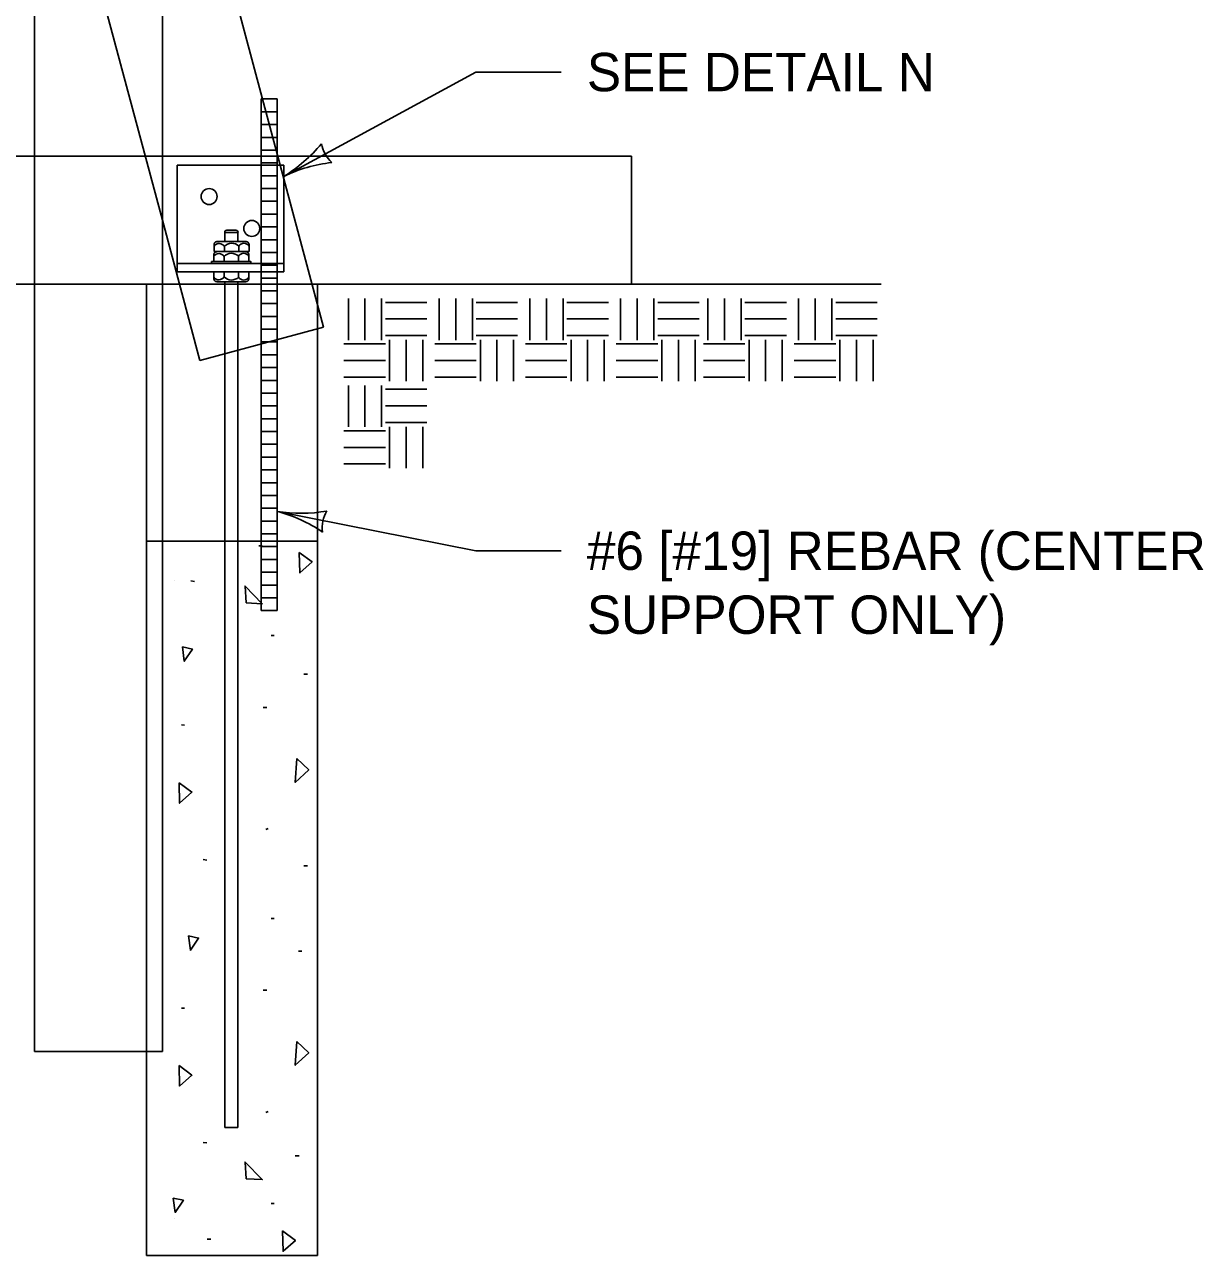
# Model space of a CAD drawing. Extents: x 49991.4 to 50021, y 49987.6 to 50011.4.
# Drawn here: x 50004.937 to 50006.78, y 49995.265 to 49997.19 of the extents above; entities that cross this region are included whole.
import ezdxf

# ---------------------------------------------------------------- set-up
doc = ezdxf.new("R2010")
doc.units = 0
for name, color, linetype in [('Level 1', 7, 'Continuous'), ('Level 2', 7, 'Continuous'), ('Level 3', 7, 'Continuous'), ('Level 4', 7, 'Continuous')]:
    doc.layers.add(name, color=color, linetype=linetype)

msp = doc.modelspace()

# ---------------------------------------------------------------- linework, layer by layer
at = {"layer": 'Level 1'}
for p, q in [((50004.9525, 49995.5838), (50004.9525, 49998.3434)), ((50005.1525, 49998.3434), (50005.1525, 49995.5838)), ((50005.3364, 49996.97), (50005.1525, 49997.6571)), ((50005.3087, 49997.0734), (50005.3316, 49997.0734)), ((50005.3316, 49996.988), (50005.3316, 49997.0734)), ((50005.3141, 49997.0534), (50005.3316, 49997.0534)), ((50005.3194, 49997.0334), (50005.3316, 49997.0334)), ((50005.3248, 49997.0134), (50005.3316, 49997.0134)), ((50005.3302, 49996.9934), (50005.3316, 49996.9934)), ((50001.0856, 49996.9838), (50004.9525, 49996.9838)), ((50005.3327, 49996.9838), (50005.8856, 49996.9838)), ((50005.8856, 49996.9838), (50005.8856, 49996.7838)), ((50005.1754, 49996.8033), (50005.1754, 49996.97)), ((50005.1754, 49996.97), (50005.3421, 49996.97)), ((50005.3421, 49996.8033), (50005.3421, 49996.97)), ((50005.4043, 49996.7164), (50005.3421, 49996.9488)), ((50005.2111, 49996.6647), (50005.1525, 49996.8838)), ((50005.2497, 49996.8648), (50005.2705, 49996.8648)), ((50005.2497, 49996.8648), (50005.2497, 49996.8506)), ((50005.253, 49996.8681), (50005.2672, 49996.8681)), ((50005.2705, 49996.8648), (50005.2705, 49996.8506)), ((50005.233, 49996.8444), (50005.233, 49996.8348)), ((50005.2818, 49996.8506), (50005.2391, 49996.8506)), ((50005.2492, 49996.8428), (50005.2492, 49996.8348)), ((50005.2717, 49996.8348), (50005.2717, 49996.8433)), ((50005.288, 49996.8348), (50005.288, 49996.8444)), ((50005.2325, 49996.8286), (50005.2325, 49996.8192)), ((50005.233, 49996.8348), (50005.288, 49996.8348)), ((50005.2488, 49996.827), (50005.2488, 49996.8192)), ((50005.2713, 49996.8192), (50005.2713, 49996.8275)), ((50005.2875, 49996.8192), (50005.2875, 49996.8286)), ((50005.1754, 49996.816), (50005.3421, 49996.816)), ((50005.1754, 49996.8033), (50005.3421, 49996.8033)), ((50005.2326, 49996.7938), (50005.2326, 49996.8033)), ((50005.2489, 49996.7954), (50005.2489, 49996.8033)), ((50005.2714, 49996.8033), (50005.2714, 49996.7949)), ((50005.2876, 49996.8033), (50005.2876, 49996.7938)), ((50004.9525, 49996.7838), (50000.2807, 49996.7838)), ((50005.1792, 49996.7838), (50005.1525, 49996.7838)), ((50005.2815, 49996.7876), (50005.2388, 49996.7876)), ((50005.2497, 49996.7876), (50005.2497, 49995.4651)), ((50005.2705, 49996.7876), (50005.2705, 49995.4651)), ((50006.2762, 49996.7838), (50005.3863, 49996.7838)), ((50005.4431, 49996.7613), (50005.4431, 49996.6965)), ((50005.469, 49996.7613), (50005.469, 49996.6965)), ((50005.495, 49996.7613), (50005.495, 49996.6965)), ((50005.585, 49996.7613), (50005.585, 49996.6965)), ((50005.6109, 49996.7613), (50005.6109, 49996.6965)), ((50005.6369, 49996.7613), (50005.6369, 49996.6965)), ((50005.7269, 49996.7613), (50005.7269, 49996.6965)), ((50005.7528, 49996.7613), (50005.7528, 49996.6965)), ((50005.7788, 49996.7613), (50005.7788, 49996.6965)), ((50005.8688, 49996.7613), (50005.8688, 49996.6965)), ((50005.8947, 49996.7613), (50005.8947, 49996.6965)), ((50005.9207, 49996.7613), (50005.9207, 49996.6965)), ((50006.0052, 49996.7613), (50006.0052, 49996.6965)), ((50006.0311, 49996.7613), (50006.0311, 49996.6965)), ((50006.0571, 49996.7613), (50006.0571, 49996.6965)), ((50006.1471, 49996.7613), (50006.1471, 49996.6965)), ((50006.173, 49996.7613), (50006.173, 49996.6965)), ((50006.199, 49996.7613), (50006.199, 49996.6965)), ((50005.501, 49996.7553), (50005.5658, 49996.7553)), ((50005.6429, 49996.7553), (50005.7077, 49996.7553)), ((50005.7848, 49996.7553), (50005.8496, 49996.7553)), ((50005.9267, 49996.7553), (50005.9915, 49996.7553)), ((50006.0631, 49996.7553), (50006.1279, 49996.7553)), ((50006.205, 49996.7553), (50006.2698, 49996.7553)), ((50005.501, 49996.7294), (50005.5658, 49996.7294)), ((50005.6429, 49996.7294), (50005.7077, 49996.7294)), ((50005.7848, 49996.7294), (50005.8496, 49996.7294)), ((50005.9267, 49996.7294), (50005.9915, 49996.7294)), ((50006.0631, 49996.7294), (50006.1279, 49996.7294)), ((50006.205, 49996.7294), (50006.2698, 49996.7294)), ((50005.2111, 49996.6647), (50005.4043, 49996.7164)), ((50005.501, 49996.7034), (50005.5658, 49996.7034)), ((50005.6429, 49996.7034), (50005.7077, 49996.7034)), ((50005.7848, 49996.7034), (50005.8496, 49996.7034)), ((50005.9267, 49996.7034), (50005.9915, 49996.7034)), ((50006.0631, 49996.7034), (50006.1279, 49996.7034)), ((50006.205, 49996.7034), (50006.2698, 49996.7034)), ((50005.3066, 49996.6903), (50005.3066, 49996.3821)), ((50005.3184, 49996.6934), (50005.3316, 49996.6934)), ((50005.3316, 49996.3821), (50005.3316, 49996.6969)), ((50005.4361, 49996.6905), (50005.501, 49996.6905)), ((50005.5075, 49996.6969), (50005.5075, 49996.6321)), ((50005.5334, 49996.6969), (50005.5334, 49996.6321)), ((50005.5594, 49996.6969), (50005.5594, 49996.6321)), ((50005.578, 49996.6905), (50005.6429, 49996.6905)), ((50005.6494, 49996.6969), (50005.6494, 49996.6321)), ((50005.6753, 49996.6969), (50005.6753, 49996.6321)), ((50005.7013, 49996.6969), (50005.7013, 49996.6321)), ((50005.7199, 49996.6905), (50005.7848, 49996.6905)), ((50005.7913, 49996.6969), (50005.7913, 49996.6321)), ((50005.8172, 49996.6969), (50005.8172, 49996.6321)), ((50005.8432, 49996.6969), (50005.8432, 49996.6321)), ((50005.8618, 49996.6905), (50005.9267, 49996.6905)), ((50005.9332, 49996.6969), (50005.9332, 49996.6321)), ((50005.9591, 49996.6969), (50005.9591, 49996.6321)), ((50005.9851, 49996.6969), (50005.9851, 49996.6321)), ((50005.9982, 49996.6905), (50006.0631, 49996.6905)), ((50006.0696, 49996.6969), (50006.0696, 49996.6321)), ((50006.0955, 49996.6969), (50006.0955, 49996.6321)), ((50006.1215, 49996.6969), (50006.1215, 49996.6321)), ((50006.1401, 49996.6905), (50006.205, 49996.6905)), ((50006.2115, 49996.6969), (50006.2115, 49996.6321)), ((50006.2374, 49996.6969), (50006.2374, 49996.6321)), ((50006.2634, 49996.6969), (50006.2634, 49996.6321)), ((50005.3066, 49996.6734), (50005.3316, 49996.6734)), ((50005.4361, 49996.6645), (50005.501, 49996.6645)), ((50005.578, 49996.6645), (50005.6429, 49996.6645)), ((50005.7199, 49996.6645), (50005.7848, 49996.6645)), ((50005.8618, 49996.6645), (50005.9267, 49996.6645)), ((50005.9982, 49996.6645), (50006.0631, 49996.6645)), ((50006.1401, 49996.6645), (50006.205, 49996.6645)), ((50005.3066, 49996.6534), (50005.3316, 49996.6534)), ((50005.3066, 49996.6334), (50005.3316, 49996.6334)), ((50005.4361, 49996.6386), (50005.501, 49996.6386)), ((50005.4431, 49996.6254), (50005.4431, 49996.5606)), ((50005.469, 49996.6254), (50005.469, 49996.5606)), ((50005.495, 49996.6254), (50005.495, 49996.5606)), ((50005.578, 49996.6386), (50005.6429, 49996.6386)), ((50005.7199, 49996.6386), (50005.7848, 49996.6386)), ((50005.8618, 49996.6386), (50005.9267, 49996.6386)), ((50005.9982, 49996.6386), (50006.0631, 49996.6386)), ((50006.1401, 49996.6386), (50006.205, 49996.6386)), ((50005.3066, 49996.6134), (50005.3316, 49996.6134)), ((50005.501, 49996.6194), (50005.5658, 49996.6194)), ((50005.3066, 49996.5934), (50005.3316, 49996.5934)), ((50005.501, 49996.5935), (50005.5658, 49996.5935)), ((50005.3066, 49996.5734), (50005.3316, 49996.5734)), ((50005.3066, 49996.5534), (50005.3316, 49996.5534)), ((50005.4361, 49996.5546), (50005.501, 49996.5546)), ((50005.501, 49996.5675), (50005.5658, 49996.5675)), ((50005.5075, 49996.561), (50005.5075, 49996.4962)), ((50005.5334, 49996.561), (50005.5334, 49996.4962)), ((50005.5594, 49996.561), (50005.5594, 49996.4962)), ((50005.3066, 49996.5334), (50005.3316, 49996.5334)), ((50005.3066, 49996.5134), (50005.3316, 49996.5134)), ((50005.4361, 49996.5286), (50005.501, 49996.5286)), ((50005.3066, 49996.4934), (50005.3316, 49996.4934)), ((50005.4361, 49996.5027), (50005.501, 49996.5027)), ((50005.3066, 49996.4734), (50005.3316, 49996.4734)), ((50005.3066, 49996.4534), (50005.3316, 49996.4534)), ((50005.3066, 49996.4334), (50005.3316, 49996.4334)), ((50005.3066, 49996.4134), (50005.3316, 49996.4134)), ((50005.1525, 49996.3821), (50005.3947, 49996.3821)), ((50005.3066, 49996.3934), (50005.3316, 49996.3934)), ((50005.3947, 49995.2651), (50005.3947, 49996.3821)), ((50005.3033, 49996.3744), (50005.3083, 49996.3744)), ((50005.1711, 49996.32), (50005.1711, 49996.32)), ((50005.1967, 49996.32), (50005.2023, 49996.3187)), ((50005.3223, 49996.2346), (50005.3273, 49996.2346)), ((50005.3733, 49996.1739), (50005.379, 49996.1739)), ((50005.3098, 49996.122), (50005.3155, 49996.122)), ((50005.1823, 49996.0946), (50005.1868, 49996.094)), ((50005.3138, 49995.9309), (50005.3178, 49995.9326)), ((50005.2161, 49995.8844), (50005.222, 49995.8832)), ((50005.3733, 49995.874), (50005.379, 49995.874)), ((50005.3223, 49995.7919), (50005.3273, 49995.7919)), ((50005.365, 49995.7409), (50005.3705, 49995.7409)), ((50005.1525, 49995.6785), (50005.1525, 49995.6785)), ((50005.3098, 49995.6796), (50005.3155, 49995.6796)), ((50005.1823, 49995.6517), (50005.1868, 49995.6517)), ((50005.1525, 49995.5838), (50004.9525, 49995.5838)), ((50005.1274, 49995.5838), (50005.1274, 49995.2651)), ((50005.3138, 49995.4884), (50005.3178, 49995.4902)), ((50005.2497, 49995.4651), (50005.2705, 49995.4651)), ((50005.2161, 49995.4416), (50005.222, 49995.4409)), ((50005.3601, 49995.4206), (50005.366, 49995.4206)), ((50005.3223, 49995.3462), (50005.3273, 49995.3462)), ((50005.1711, 49995.3234), (50005.1711, 49995.3234)), ((50005.2223, 49995.2907), (50005.2278, 49995.2907)), ((50005.1274, 49995.2651), (50005.3947, 49995.2651))]:
    msp.add_line(p, q, dxfattribs=at)
for points in [[(50005.2291, 49996.816), (50005.2907, 49996.816), (50005.2907, 49996.8192), (50005.2291, 49996.8192)], [(50005.3663, 49996.3644), (50005.3864, 49996.3498), (50005.3673, 49996.3324)], [(50005.2831, 49996.2854), (50005.3083, 49996.284), (50005.2815, 49996.3116)], [(50005.1837, 49996.2165), (50005.1865, 49996.1942), (50005.1993, 49996.2132)], [(50005.3623, 49996.0419), (50005.3811, 49996.0246), (50005.36, 49996.0047)], [(50005.1783, 49996.0042), (50005.1985, 49995.9897), (50005.1793, 49995.9722)], [(50005.1932, 49995.7646), (50005.1961, 49995.7423), (50005.2089, 49995.7613)], [(50005.3623, 49995.5996), (50005.3811, 49995.5816), (50005.36, 49995.5624)], [(50005.1783, 49995.5619), (50005.1985, 49995.5469), (50005.1793, 49995.5299)], [(50005.2831, 49995.3849), (50005.3083, 49995.3837), (50005.2815, 49995.411)], [(50005.1694, 49995.3548), (50005.1723, 49995.3324), (50005.1851, 49995.3514)], [(50005.3401, 49995.3036), (50005.3602, 49995.2886), (50005.3411, 49995.2716)]]:
    msp.add_lwpolyline(points, close=True, dxfattribs=at)
for centre in [(50005.2254, 49996.9209), (50005.2921, 49996.8709)]:
    msp.add_circle(centre, 0.0125, dxfattribs=at)
for centre, radius, start, end in [((50005.253, 49996.8648), 0.00333, 90, 180), ((50005.2672, 49996.8648), 0.00333, 0, 90), ((50005.2409, 49996.8377), 0.00975, 31.3232, 143.8927), ((50005.2607, 49996.8324), 0.0155, 44.7321, 137.9001), ((50005.2798, 49996.8382), 0.00956, 31.4819, 147.9066), ((50005.2405, 49996.822), 0.00975, 31.3232, 144.6472), ((50005.2603, 49996.8166), 0.0155, 44.7321, 137.9001), ((50005.2794, 49996.8225), 0.00956, 32.3321, 147.9066), ((50005.2405, 49996.8004), 0.00975, 215.6058, 328.6768), ((50005.2604, 49996.8058), 0.0155, 222.0999, 315.2679), ((50005.2795, 49996.7999), 0.00956, 212.0934, 327.9491)]:
    msp.add_arc(centre, radius, start, end, dxfattribs=at)
for points in [[(50005.233, 49996.8444), (50005.233, 49996.8447), (50005.233, 49996.845), (50005.233, 49996.8454), (50005.2331, 49996.8456), (50005.2331, 49996.846), (50005.2331, 49996.8462), (50005.2332, 49996.8465), (50005.2333, 49996.8468), (50005.2333, 49996.847), (50005.2335, 49996.8473), (50005.2335, 49996.8476), (50005.2337, 49996.8478), (50005.2338, 49996.848), (50005.2339, 49996.8482), (50005.2341, 49996.8484), (50005.2342, 49996.8486), (50005.2343, 49996.8488), (50005.2345, 49996.849), (50005.2347, 49996.8492), (50005.2349, 49996.8493), (50005.2351, 49996.8494), (50005.2353, 49996.8496), (50005.2355, 49996.8498), (50005.2357, 49996.8498), (50005.2359, 49996.85), (50005.2362, 49996.85), (50005.2365, 49996.8502), (50005.2367, 49996.8502), (50005.237, 49996.8503), (50005.2373, 49996.8504), (50005.2376, 49996.8504), (50005.2379, 49996.8504), (50005.2382, 49996.8505), (50005.2385, 49996.8505), (50005.2388, 49996.8506), (50005.2391, 49996.8506)], [(50005.288, 49996.8444), (50005.288, 49996.8447), (50005.2879, 49996.845), (50005.2879, 49996.8454), (50005.2879, 49996.8456), (50005.2879, 49996.846), (50005.2878, 49996.8462), (50005.2877, 49996.8465), (50005.2877, 49996.8468), (50005.2876, 49996.847), (50005.2875, 49996.8473), (50005.2874, 49996.8476), (50005.2873, 49996.8478), (50005.2872, 49996.848), (50005.2871, 49996.8482), (50005.2869, 49996.8484), (50005.2867, 49996.8486), (50005.2866, 49996.8488), (50005.2864, 49996.849), (50005.2863, 49996.8492), (50005.2861, 49996.8493), (50005.2859, 49996.8494), (50005.2857, 49996.8496), (50005.2855, 49996.8498), (50005.2852, 49996.8498), (50005.285, 49996.85), (50005.2847, 49996.85), (50005.2845, 49996.8502), (50005.2842, 49996.8502), (50005.2839, 49996.8503), (50005.2837, 49996.8504), (50005.2834, 49996.8504), (50005.2831, 49996.8504), (50005.2828, 49996.8505), (50005.2825, 49996.8505), (50005.2821, 49996.8506), (50005.2818, 49996.8506)], [(50005.2325, 49996.8286), (50005.2325, 49996.829), (50005.2326, 49996.8292), (50005.2326, 49996.8296), (50005.2326, 49996.8299), (50005.2327, 49996.8302), (50005.2327, 49996.8305), (50005.2328, 49996.8308), (50005.2329, 49996.831), (50005.2329, 49996.8313), (50005.233, 49996.8316), (50005.2331, 49996.8318), (50005.2332, 49996.832), (50005.2333, 49996.8322), (50005.2335, 49996.8325), (50005.2336, 49996.8327), (50005.2338, 49996.8329), (50005.2339, 49996.833), (50005.2341, 49996.8332), (50005.2343, 49996.8334), (50005.2345, 49996.8336), (50005.2347, 49996.8337), (50005.2349, 49996.8338), (50005.2351, 49996.834), (50005.2353, 49996.8341), (50005.2355, 49996.8342), (50005.2358, 49996.8343), (50005.236, 49996.8344), (50005.2363, 49996.8345), (50005.2366, 49996.8346), (50005.2369, 49996.8346), (50005.2371, 49996.8346), (50005.2375, 49996.8347), (50005.2377, 49996.8348), (50005.2381, 49996.8348), (50005.2384, 49996.8348), (50005.2387, 49996.8348)], [(50005.2875, 49996.8286), (50005.2875, 49996.829), (50005.2875, 49996.8292), (50005.2875, 49996.8296), (50005.2875, 49996.8299), (50005.2874, 49996.8302), (50005.2874, 49996.8305), (50005.2873, 49996.8308), (50005.2873, 49996.831), (50005.2872, 49996.8313), (50005.2871, 49996.8316), (50005.287, 49996.8318), (50005.2869, 49996.832), (50005.2867, 49996.8322), (50005.2866, 49996.8325), (50005.2865, 49996.8327), (50005.2863, 49996.8329), (50005.2862, 49996.833), (50005.286, 49996.8332), (50005.2858, 49996.8334), (50005.2857, 49996.8336), (50005.2855, 49996.8337), (50005.2853, 49996.8338), (50005.285, 49996.834), (50005.2848, 49996.8341), (50005.2846, 49996.8342), (50005.2843, 49996.8343), (50005.2841, 49996.8344), (50005.2838, 49996.8345), (50005.2835, 49996.8346), (50005.2833, 49996.8346), (50005.2829, 49996.8346), (50005.2827, 49996.8347), (50005.2823, 49996.8348), (50005.282, 49996.8348), (50005.2817, 49996.8348), (50005.2814, 49996.8348)], [(50005.2326, 49996.7938), (50005.2326, 49996.7934), (50005.2327, 49996.7931), (50005.2327, 49996.7928), (50005.2327, 49996.7925), (50005.2327, 49996.7922), (50005.2328, 49996.7919), (50005.2329, 49996.7916), (50005.2329, 49996.7914), (50005.233, 49996.791), (50005.2331, 49996.7908), (50005.2332, 49996.7906), (50005.2333, 49996.7904), (50005.2334, 49996.7901), (50005.2335, 49996.7899), (50005.2337, 49996.7897), (50005.2339, 49996.7895), (50005.234, 49996.7893), (50005.2342, 49996.7892), (50005.2343, 49996.789), (50005.2345, 49996.7888), (50005.2347, 49996.7886), (50005.2349, 49996.7885), (50005.2351, 49996.7884), (50005.2354, 49996.7882), (50005.2356, 49996.7882), (50005.2359, 49996.788), (50005.2361, 49996.788), (50005.2364, 49996.7879), (50005.2367, 49996.7878), (50005.2369, 49996.7878), (50005.2372, 49996.7877), (50005.2375, 49996.7876), (50005.2378, 49996.7876), (50005.2381, 49996.7876), (50005.2385, 49996.7876), (50005.2388, 49996.7876)], [(50005.2876, 49996.7938), (50005.2876, 49996.7934), (50005.2876, 49996.7931), (50005.2876, 49996.7928), (50005.2875, 49996.7925), (50005.2875, 49996.7922), (50005.2875, 49996.7919), (50005.2874, 49996.7916), (50005.2873, 49996.7914), (50005.2873, 49996.791), (50005.2871, 49996.7908), (50005.2871, 49996.7906), (50005.2869, 49996.7904), (50005.2868, 49996.7901), (50005.2867, 49996.7899), (50005.2865, 49996.7897), (50005.2864, 49996.7895), (50005.2863, 49996.7893), (50005.2861, 49996.7892), (50005.2859, 49996.789), (50005.2857, 49996.7888), (50005.2855, 49996.7886), (50005.2853, 49996.7885), (50005.2851, 49996.7884), (50005.2849, 49996.7882), (50005.2847, 49996.7882), (50005.2844, 49996.788), (50005.2841, 49996.788), (50005.2839, 49996.7879), (50005.2836, 49996.7878), (50005.2833, 49996.7878), (50005.283, 49996.7877), (50005.2827, 49996.7876), (50005.2824, 49996.7876), (50005.2821, 49996.7876), (50005.2818, 49996.7876), (50005.2815, 49996.7876)]]:
    msp.add_spline(points, degree=3, dxfattribs=at)
at = {"layer": 'Level 3'}
for p, q in [((50005.6424, 49997.1155), (50005.3421, 49996.9524)), ((50005.776, 49997.1155), (50005.6424, 49997.1155)), ((50005.6424, 49996.367), (50005.3316, 49996.4285)), ((50005.776, 49996.367), (50005.6424, 49996.367))]:
    msp.add_line(p, q, dxfattribs=at)
for centre, radius, start, end in [((50005.2209, 49997.1514), 0.233, 301.34, 320.5898), ((50005.4548, 49997.0136), 0.0548, 190.6515, 226.3739), ((50005.4401, 49996.7528), 0.2223, 95.9687, 116.1522), ((50005.3686, 49996.6585), 0.233, 260.8611, 280.1109), ((50005.2766, 49996.2131), 0.2223, 55.4898, 75.6733), ((50005.457, 49996.4019), 0.0548, 150.1726, 185.895)]:
    msp.add_arc(centre, radius, start, end, dxfattribs=at)
at = {"layer": 'Level 4'}
for p, q in [((50005.1525, 49996.8838), (50004.9525, 49997.6307)), ((50005.3066, 49996.6903), (50005.3066, 49997.0734)), ((50005.3066, 49997.0734), (50005.3087, 49997.0734)), ((50005.3066, 49997.0534), (50005.3141, 49997.0534)), ((50005.3066, 49997.0334), (50005.3194, 49997.0334)), ((50005.3066, 49997.0134), (50005.3248, 49997.0134)), ((50005.3066, 49996.9934), (50005.3302, 49996.9934)), ((50004.9525, 49996.9838), (50005.3327, 49996.9838)), ((50005.3066, 49996.9734), (50005.3316, 49996.9734)), ((50005.3316, 49996.6969), (50005.3316, 49996.988)), ((50005.3066, 49996.9534), (50005.3316, 49996.9534)), ((50005.3364, 49996.97), (50005.3421, 49996.9488)), ((50005.3066, 49996.9334), (50005.3316, 49996.9334)), ((50005.3066, 49996.9134), (50005.3316, 49996.9134)), ((50005.3066, 49996.8934), (50005.3316, 49996.8934)), ((50005.3066, 49996.8734), (50005.3316, 49996.8734)), ((50005.3066, 49996.8534), (50005.3316, 49996.8534)), ((50005.3066, 49996.8334), (50005.3316, 49996.8334)), ((50005.3066, 49996.8134), (50005.3316, 49996.8134)), ((50005.1525, 49996.7838), (50004.9525, 49996.7838)), ((50005.1274, 49996.7838), (50005.1274, 49995.5838)), ((50005.3863, 49996.7838), (50005.1792, 49996.7838)), ((50005.3066, 49996.7934), (50005.3316, 49996.7934)), ((50005.3947, 49996.3821), (50005.3947, 49996.7838)), ((50005.3066, 49996.7734), (50005.3316, 49996.7734)), ((50005.3066, 49996.7534), (50005.3316, 49996.7534)), ((50005.3066, 49996.7334), (50005.3316, 49996.7334)), ((50005.3066, 49996.7134), (50005.3316, 49996.7134)), ((50005.3066, 49996.6934), (50005.3184, 49996.6934)), ((50005.1525, 49996.3821), (50005.1274, 49996.3821)), ((50005.3066, 49996.3821), (50005.3066, 49996.2734)), ((50005.3316, 49996.2734), (50005.3316, 49996.3821)), ((50005.3066, 49996.3734), (50005.3316, 49996.3734)), ((50005.3066, 49996.3534), (50005.3316, 49996.3534)), ((50005.3066, 49996.3334), (50005.3316, 49996.3334)), ((50005.3066, 49996.3134), (50005.3316, 49996.3134)), ((50005.3066, 49996.2934), (50005.3316, 49996.2934)), ((50005.3066, 49996.2734), (50005.3316, 49996.2734))]:
    msp.add_line(p, q, dxfattribs=at)

# ---------------------------------------------------------------- texts
at = {"layer": 'Level 2'}
for s, p in [('SEE DETAIL N', (50005.816, 49997.0855)), ('#6 [#19] REBAR (CENTER', (50005.816, 49996.337)), ('SUPPORT ONLY)', (50005.816, 49996.237))]:
    msp.add_text(s, height=0.06, dxfattribs=at).set_placement(p)

doc.saveas('drawing.dxf')
